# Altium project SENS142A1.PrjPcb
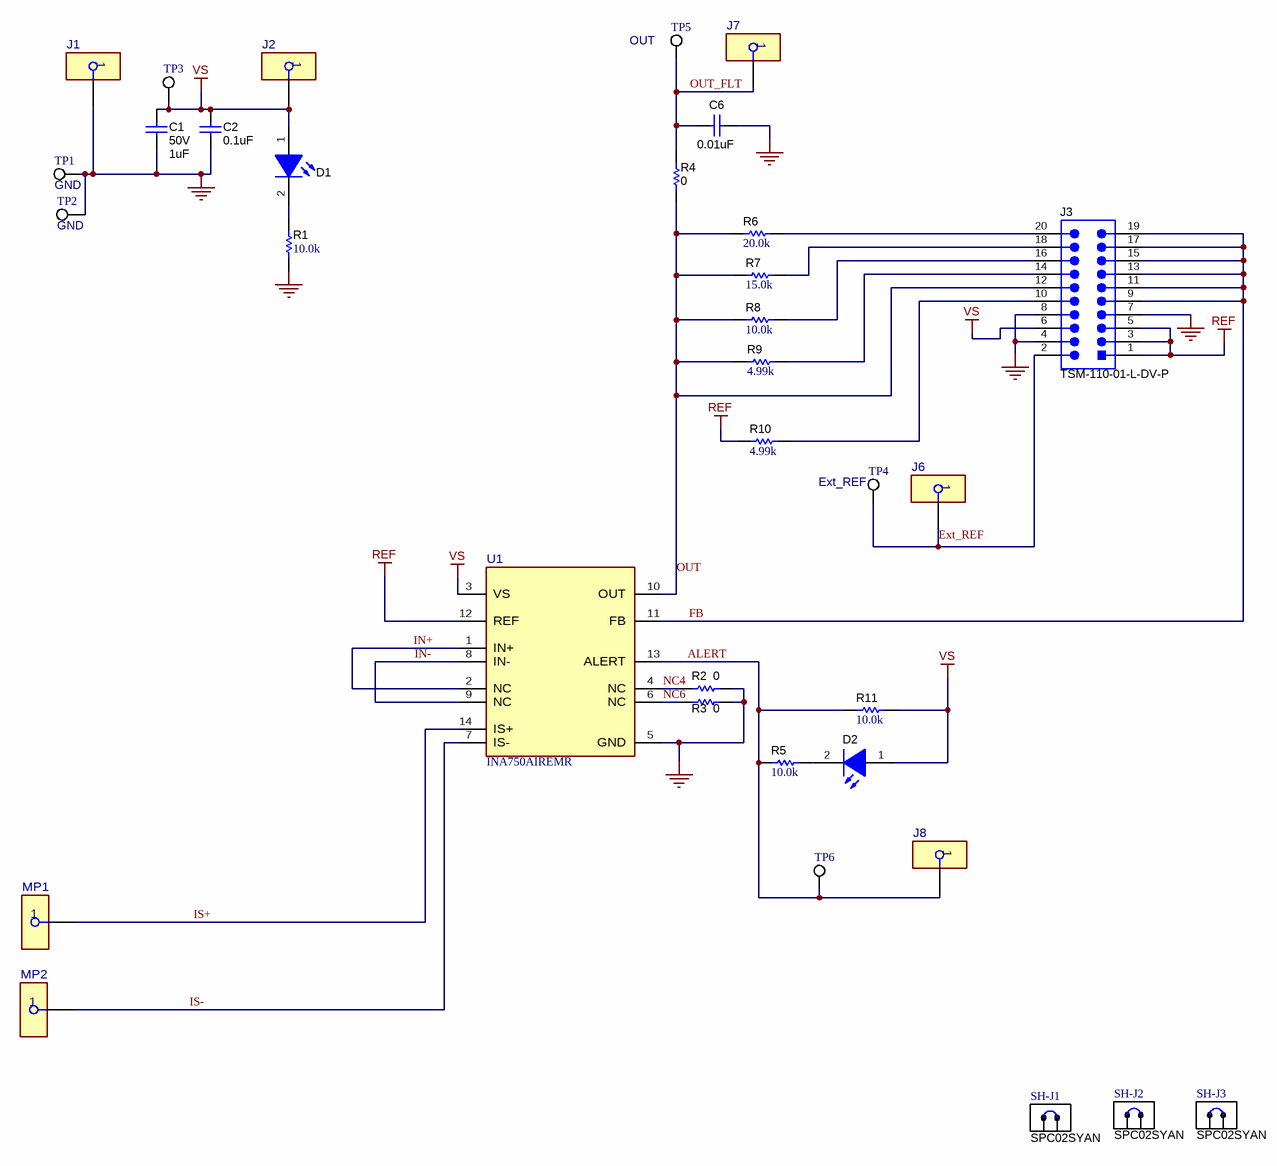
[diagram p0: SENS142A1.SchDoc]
CopyrightYear: 2024; PCB_Layout: G Zhou; PCB_Rev: A1; PRJ_Customer: Public Release; PRJ_Engineer: G Zhou; PRJ_Number: SENS142; PRJ_Title: INA750-INA751EVM; SCH_Rev: A1; TechSupport: http://www.ti.com/support; TID: N/A
2 sheets, 51 parts. Net scope: global (net labels, ports and power ports of the same name join across sheets).
Board file: SENS142A1.PcbDoc
Sheets:
  SENS142A1.SchDoc
  SENS142A1_HW.SchDoc

## Sheet SENS142A1.SchDoc
size 431 x 279 mm; Date: Not shown in title block; ApprovedBy: Not shown in title block; CheckedBy: Not shown in title block; Author: Not shown in title block; CompanyName: Not shown in title block; Engineer: Not shown in title block; Organization: Not shown in title block; Address1: Not shown in title block; Address2: Not shown in title block; Address3: Not shown in title block; Address4: Not shown in title block; DocumentNumber: 2; Revision: Use project parameter SCH_Rev; SheetNumber: 2; SheetTotal: 3; PageSetup: Record=PageOptions¦CenterHorizontal=True¦CenterVertical=True¦PrintScale=1.00¦XCorrection=1.00¦YCorrection=1.00¦PrintKind=0¦BorderSize=5000000¦LeftOffset=0¦BottomOffset=0¦Orientation=2¦PaperLength=1000¦PaperWidth=1000¦Scale=100¦PaperSource=15¦PrintQuality=600¦MediaType=1¦DitherType=10¦PaperKind=Letter¦PrintScaleMode=1

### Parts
C1  VDC_V: 50V  ValueDisplayed: 1uF  [0603]  (hidden comment: C1608X6S1H105K080AC)
C2  ValueDisplayed: 0.1uF  [0402]  (hidden comment: GRM155R71H104ME14D)
C6  ValueDisplayed: 0.01uF  [0402]  (hidden comment: CGA2B3X7S2A103K050BB)
D1  POWER  [VAOL-0805_White]  (value not drawn)
D2  ALERT  [VAOL-0805_White]  (value not drawn)
J1  (no value)  [FP-3-331272-8_PIN_RCPT-MFG]
J2  (no value)  [FP-3-331272-8_PIN_RCPT-MFG]
J3  TSM-110-01-L-DV-P  [CONN_TSM-110-01-T-DV-P]
J6  (no value)  [FP-3-331272-8_PIN_RCPT-MFG]
J7  (no value)  [FP-3-331272-8_PIN_RCPT-MFG]
J8  (no value)  [FP-3-331272-8_PIN_RCPT-MFG]
MP1  CB70-14-190  [FP-CB70-14-190_CONN_TERM_RECT_LUG-MFG]  (value not drawn)
MP2  CB70-14-190  [FP-CB70-14-190_CONN_TERM_RECT_LUG-MFG]  (value not drawn)
R1  ValueDisplayed: 10.0k  [0402]  (hidden comment: CRCW040210K0FKED)
R2  ValueDisplayed: 0  [0402]  (hidden comment: RC0402JR-070RL)
R3  ValueDisplayed: 0  [0402]  (hidden comment: RC0402JR-070RL)
R4  ValueDisplayed: 0  [0402]  (hidden comment: RC0402JR-070RL)
R5  ValueDisplayed: 10.0k  [0402]  (hidden comment: CRCW040210K0FKED)
R6  ValueDisplayed: 20.0k  [0402]  (hidden comment: CRCW040220K0FKED)
R7  ValueDisplayed: 15.0k  [0402]  (hidden comment: CRCW040215K0FKED)
R8  ValueDisplayed: 10.0k  [0402]  (hidden comment: CRCW040210K0FKED)
R9  ValueDisplayed: 4.99k  [0402]  (hidden comment: CRCW04024K99FKED)
R10  ValueDisplayed: 4.99k  [0402]  (hidden comment: CRCW04024K99FKED)
R11  ValueDisplayed: 10.0k  [0402]  (hidden comment: CRCW040210K0FKED)
SH-J1  SPC02SYAN  [SPC02SYAN]
SH-J2  SPC02SYAN  [SPC02SYAN]
SH-J3  SPC02SYAN  [SPC02SYAN]
TP1  GND  [Testpoint_Keystone_Miniature]
TP2  GND  [Testpoint_Keystone_Miniature]
TP3  VS  [Testpoint_Keystone_Miniature]  (value not drawn)
TP4  Ext_REF  [Testpoint_Keystone_Miniature]
TP5  OUT  [Testpoint_Keystone_Miniature]
TP6  (no value)  [Testpoint_Keystone_Miniature]
U1  INA750AIREMR  [REM0014B-MFG]

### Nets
GND: C1.2 C2.2 C6.1 J1.1 J3.4 J3.7 J3.8 R1.1 R2.2 R3.2 TP1.1 TP2.1 U1.5(GND)
REF: J3.1 J3.3 J3.5 R10.1 U1.12(REF)
VS: C1.1 C2.1 D1.1(A) D2.1(A) J2.1 J3.6 R11.1 TP3.1 U1.3(VS)
ALERT: J8.1 R5.2 R11.2 TP6.1 U1.13(ALERT)
Ext_REF: J3.2 J6.1 TP4.1
FB: J3.9 J3.11 J3.13 J3.15 J3.17 J3.19 U1.11(FB)
IN+: U1.1(IN+) U1.2(NC)
IN-: U1.8(IN-) U1.9(NC)
IS+: MP1.1 U1.14(IS+)
IS-: MP2.1 U1.7(IS-)
NC4: R2.1 U1.4(NC)
NC6: R3.1 U1.6(NC)
OUT: J3.12 R4.1 R6.1 R7.1 R8.2 R9.1 U1.10(OUT)
OUT_FLT: C6.2 J7.1 R4.2 TP5.1
NetD1_2: D1.2(K) R1.2
NetD2_2: D2.2(K) R5.1
NetJ3_10: J3.10 R10.2
NetJ3_14: J3.14 R9.2
NetJ3_16: J3.16 R8.1
NetJ3_18: J3.18 R7.2
NetJ3_20: J3.20 R6.2

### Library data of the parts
C1 = CMP-0007029-4: CAP, CERM, 1 uF, 50 V, +/- 10%, X6S, 0603; Manufacturer: TDK; TaMin_C: -55°C; ESR_ohm: 5.522m; Polarized: N; SizeAreaWB_mm2: 4.68; Value1: 0.005522 ohm; U/M: EA; Value: 1uF; TaMax_C: 105°C; SizeZ_mm: 1; SizeX_mm: 1.6; SizeY_mm: 0.8; SizeArea_mm2: 1.28; Cap_F: 1µF; IRMS_A: 2.21617A; AEC Category: Q200
C2 = CMP-0006675-2: CAP, CERM, 0.1 uF, 50 V, +/- 20%, X7R, 0402; Manufacturer: MuRata; Polarized: N; Value: 0.1uF; U/M: EA; Cap_F: 100nF; Value1: Unknown; VDC_V: 50V; TaMin_C: -55°C; TaMax_C: 125°C; SizeArea_mm2: 0.5; SizeAreaWB_mm2: 3; SizeX_mm: 1; SizeZ_mm: 0.6; AEC Category: Q200
C6 = CMP-0006333-1: CAP, CERM, 0.01 uF, 100 V, +/- 10%, X7S, AEC-Q200 Grade 1, 0402; Manufacturer: TDK; TaMin_C: -55°C; ESR_ohm: 0.410191; Polarized: N; SizeAreaWB_mm2: 3; Value1: 0.410191 ohm; U/M: EA; Value: 0.01uF; TaMax_C: 125°C; SizeZ_mm: 0.6; SizeX_mm: 1; SizeY_mm: 0.5; Value2: 100V; AEC Qualified: Y; Cap_F: 10nF; IRMS_A: 291.729mA; AEC Category: Q200
D1 D2 = CMP-0002885-2: LED, White, SMD; PartNumber: VAOL-S8WR4; Manufacturer: Visual Communications Company, LLC; Type: InGaN; Value1: W; Io_A: 5mA; Vf_V: 2.925V
J1 J2 J6-J8 = CMP-0086763-1: CONN PIN RCPT .018-.021 SOLDER; PartNumber: 3-331272-8; Manufacturer: TE Connectivity; ContactFinish: Gold,Nickel; Current_A: 5A
J3 = CMP-0075600-2: Header, 2.54mm, 10x2, Gold, SMT; Manufacturer: Samtec; Pitch_mm: 2.54; Gender: Male; Cert_CSA: Y; Green_REACh: Passed; Current_A: 5.4A; Voltage_V: 475V; Shrouded: N; Green_Lifecycle: Active; Row_Count: 2
MP1 MP2 = CMP-0121463-2: Terminal Connector Rectangular Lug, Grounding 1/4 Stud; Manufacturer: Panduit; Current_A: 90A; Voltage_V: 600V; AEC Qualified: No; Is Female: yes; Conn Gender: Female; Conn Orientation: Horizontal; Max Wire Gauge: 2; Min Wire Gauge: 8
R1 R5 R8 R11 = CMP-0025958-3: RES, 10.0 k, 1%, 0.063 W, AEC-Q200 Grade 0, 0402; Manufacturer: Vishay-Dale; Power_W: 63mW; TempCo: 100 ppm/C; Value_Code: 10k0; Value: 10.0k; EIA_Code: E96; Res_ohm: 10k; SizeX_mm: 1; SizeY_mm: 0.5; SizeZ_mm: 0.6; Value2: 0.063W; AEC Qualified: Y; VDC_V: 50V; AEC Category: Q200; AEC Grade: 0
R2-R4 = CMP-0027004-2: RES, 0, 5%, 0.063 W, 0402; Manufacturer: Yageo America; Power_W: 63mW; TempCo: 200 ppm/C; Value_Code: 0000; U/M: EA; Value: 0; EIA_Code: E24; SizeX_mm: 1; SizeY_mm: 0.5; SizeZ_mm: 0.6; Value2: 0.063W; VDC_V: 50V; AEC Category: Q200
R6 = CMP-0026162-1: RES, 20.0 k, 1%, 0.063 W, 0402; Manufacturer: Vishay-Dale; Power_W: 63mW; TempCo: 100 ppm/C; Value_Code: 20k0; U/M: EA; Value: 20.0k; EIA_Code: E96; Res_ohm: 20k; SizeX_mm: 1; SizeY_mm: 0.5; SizeZ_mm: 0.6; Value2: 0.063W; VDC_V: 50V; AEC Category: Q200
R7 = CMP-0026027-2: RES, 15.0 k, 1%, 0.063 W, 0402; Manufacturer: Vishay-Dale; Power_W: 63mW; TempCo: 100 ppm/C; Value_Code: 15k0; U/M: EA; Value: 15.0k; EIA_Code: E96; Res_ohm: 15k; SizeX_mm: 1; SizeY_mm: 0.5; SizeZ_mm: 0.6; Value2: 0.063W; VDC_V: 50V; AEC Category: Q200
R9 R10 = CMP-0026414-1: RES, 4.99 k, 1%, 0.063 W, 0402; Manufacturer: Vishay-Dale; Power_W: 63mW; TempCo: 100 ppm/C; Value_Code: 4k99; U/M: EA; Value: 4.99k; EIA_Code: E96; SizeX_mm: 1; SizeY_mm: 0.5; SizeZ_mm: 0.6; Value2: 0.063W; VDC_V: 50V; AEC Category: Q200
SH-J1-SH-J3 = CMP-0003642-1: Shunt, 100mil, Flash Gold, Black; Manufacturer: Sullins Connector Solutions; Value: 1x2
TP1-TP6 = CMP-0055152-1: Test Point, Miniature, SMT; Manufacturer: Keystone; CNHeader: FALSE; Green_Lifecycle: Active; Green_REACh: Passed; CT: TRUE
U1 = CMP-0122809-2: -4V to 110V, Bidirectional, Ultra-Precise, Current Sense Amplifier with Enhanced PWM Rejection and 35A EZShuntTM Technology; Manufacturer: Texas Instruments; SizeZ_mm: 1mm; AEC Qualified: No; Bandwidth: 1MHz; Input Offset Voltage: 65mV; Max Supply Voltage: 5.5V; Min Supply Voltage: 2.7V; Nominal Supply Current: 3.5mA; Number Of Channels: 1; Output Current Per Channel: 25A; Response Time: 2.5us; Standoff Height: 0mm; TaMax_C: +125°C; TaMin_C: -40°C; TJmax_C: +150°C; AEC Category: Q200; CompType: IC

## Sheet SENS142A1_HW.SchDoc
size 431 x 279 mm; Date: Not shown in title block; ApprovedBy: Not shown in title block; CheckedBy: Not shown in title block; Author: Not shown in title block; CompanyName: Not shown in title block; Engineer: Not shown in title block; Organization: Not shown in title block; Address1: Not shown in title block; Address2: Not shown in title block; Address3: Not shown in title block; Address4: Not shown in title block; DocumentNumber: 3; Revision: Use project parameter SCH_Rev; SheetNumber: 3; SheetTotal: 3; PageSetup: Record=PageOptions¦CenterHorizontal=True¦CenterVertical=True¦PrintScale=1.00¦XCorrection=1.00¦YCorrection=1.00¦PrintKind=0¦BorderSize=5000000¦LeftOffset=0¦BottomOffset=0¦Orientation=2¦PaperLength=1000¦PaperWidth=1000¦Scale=100¦PaperSource=15¦PrintQuality=600¦MediaType=1¦DitherType=10¦PaperKind=Letter¦PrintScaleMode=1
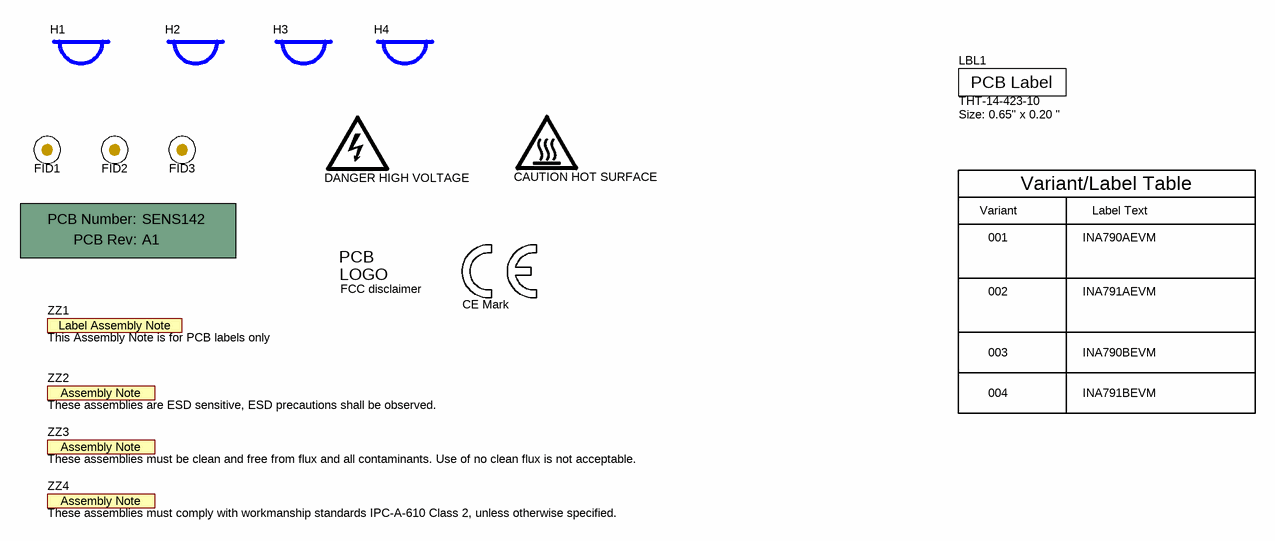
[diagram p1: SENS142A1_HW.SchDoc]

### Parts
!PCB1  Printed Circuit Board  (value not drawn)  (mechanical)
FID1  Fiducial  [Fiducial10-20]  (value not drawn)
FID2  Fiducial  [Fiducial10-20]  (value not drawn)
FID3  Fiducial  [Fiducial10-20]  (value not drawn)
H1  SJ61A2  [Bumpon_SJ61A2]  (value not drawn)
H2  SJ61A2  [Bumpon_SJ61A2]  (value not drawn)
H3  SJ61A2  [Bumpon_SJ61A2]  (value not drawn)
H4  SJ61A2  [Bumpon_SJ61A2]  (value not drawn)
LBL1  THT-14-423-10  Note: Size: 0.65" x 0.20 "  [Label_650x200]
LOGO1  DANGER HIGH VOLTAGE  [IEC_HighVoltage_Medium]  (no BOM)
Logo2  FCC disclaimer  [FCC_disclaimer]  (no BOM)
LOGO3  CE Mark  [CE_Mark_5mm]  (no BOM)
Logo4  CAUTION HOT SURFACE  [IEC_HotSurface_Medium]  (no BOM)
ZZ1  This Assembly Note is for PCB labels only  [AssemblyNoteLabel]  (no BOM)
ZZ2  These assemblies are ESD sensitive, ESD precautions shall be observed.  [AssemblyNote]  (no BOM)
ZZ3  These assemblies must be clean and free from flux and all contaminants. Use of no clean flux is not acceptable.  [AssemblyNote]  (no BOM)
ZZ4  These assemblies must comply with workmanship standards IPC-A-610 Class 2, unless otherwise specified.  [AssemblyNote]  (no BOM)

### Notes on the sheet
- Variant
- Variant/Label Table
- Label Text
- 001
- INA790AEVM
- 002
- 003
- INA791AEVM
- INA790BEVM
- 004
- INA791BEVM

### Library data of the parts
!PCB1 = CMP-0003618-2: Manufacturer: Any; PartNumber: SENS142
FID1-FID3 = CMP-0077181-1: Fiducial mark.  There is nothing to buy or mount.
H1-H4 = CMP-0003622-1: Bumpon, Hemisphere, 0.375 X 0.235, Black; Manufacturer: 3M
LBL1 = CMP-0003625-1: Thermal Transfer Printable Labels, 0.650" W x 0.200" H - 10,000 per roll; Manufacturer: Brady; CompType: Label
LOGO1 = CMP-0074835-1: IEC 61010-1 High Voltage Warning; SymbolCreator: a0412235
Logo2 = CMP-0074847-1: FCC_disclaimer
LOGO3 = CMP-0074844-1: SymbolCreator: a0412235
Logo4 = CMP-0074837-2: IEC 61010-1 Hot Surface Warning; Manufacturer: Texas Instruments; CompType: IC; AEC Category: Q200; SymbolCreator: a0412235
ZZ1 = CMP-0003616-3
ZZ2 = CMP-0077236-1
ZZ3 = CMP-0077237-1
ZZ4 = CMP-0077238-1

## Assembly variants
001: not fitted C6 FID1 FID2 FID3 R2 R3
002: not fitted C6 FID1 FID2 FID3 R2 R3
003: not fitted C6 FID1 FID2 FID3 R2 R3
004: not fitted C6 FID1 FID2 FID3 R2 R3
